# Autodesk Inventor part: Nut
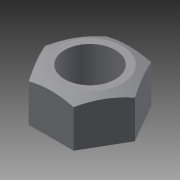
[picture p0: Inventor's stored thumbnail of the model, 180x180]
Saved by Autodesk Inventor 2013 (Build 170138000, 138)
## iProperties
Created: 2004-07
Part Number: Nut
Document SubType Name: Modeling
Designer: Autodesk, Inc.
Manufacturer: Standard
Standards Organization: Custom
Density: 1 g/cm^3
Mass: 3.54479 g
Surface Area: 21.3114 cm^2
Volume: 3.54479 cm^3
Material: Generic
Author: Autodesk, Inc.
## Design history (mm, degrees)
sketch "Sketch1"
  geometry: L1 (-13.279, 0)-(-6.64, 11.5); L2 (-6.64, 11.5)-(6.64, 11.5); L3 (6.64, 11.5)-(13.279, 0); L4 (13.279, 0)-(6.64, -11.5); L5 (6.64, -11.5)-(-6.64, -11.5); L6 (-6.64, -11.5)-(-13.279, 0); 2 further points
  constraints: 12 end point, 1 coincident, 11 other
  dimensions: "d0" = 23 distance between parallel lines of L2 L5
extrude "Extrusion1" new body sketch "Sketch1" distance "d1" = 13; taper "d2" = 0 deg
sketch "Sketch2"
  geometry: L1 (0, -2.8)-(0, 16.8) reference; L2 (13.6, 14)-(13.6, 11); L3 (13.6, 11)-(7.6, 14); L4 (7.6, 14)-(13.6, 14); L5 (13.279, 0)-(6.64, 0) reference; L6 (6.64, 0)-(-6.64, 0) reference; L7 (-6.64, 0)-(-13.279, 0) reference; L8 (-13.279, 0)-(-6.64, 0) reference; L9 (-6.64, 0)-(6.64, 0) reference; L10 (6.64, 0)-(13.279, 0) reference
  constraints: 6 end point, 1 parallel, 1 perpendicular
  dimensions: "d3" = 27.2 diameter of L2 L1; "d4" = 6 distance of L3.end L2.start; "d5" = 3 distance of L2.start L2.end; "d6" = 14 distance between parallel lines of L4 L5
revolve "Revolution1" sketch "Sketch2" stored, may be unused: angle "d7" = 90 deg
sketch "Sketch3"
  geometry: C1 r 7.5 at (0, 0); 1 further point
  constraints: 1 centre point, 1 coincident
  dimensions: "d8" = 15 diameter of C1
extrude "Extrusion2" cut sketch "Sketch3" stored distance "d9" = 13; taper "d10" = 0 deg
body "Solid1"
node "Projected Loop1"
